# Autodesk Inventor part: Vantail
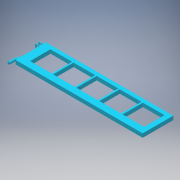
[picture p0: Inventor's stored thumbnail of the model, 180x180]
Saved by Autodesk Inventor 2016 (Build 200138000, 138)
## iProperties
Shininess: 20.0
Length Units: 11269
Angle Units: 11279
Time Units: 11290
Mass Units: 11283
Length Display Precision: 3
Angle Display Precision: 2
Part Number: Vantail
Material: Acier
Document SubType Name: Modeling
Created: 2007-01
Designer: plantier
Mass: 24887.6 g
Surface Area: 3922.97 cm^2
Volume: 3170.39 cm^3
Density: 7.85 g/cm^3
Appearance: Bleu (ciel - vif)
Density: 0.0
Volumn: 0.0
Area: 0.0
PropertySet Name: Model Information
Control State: 0
Master: False
Checked Out: False
Author: plantier
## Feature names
1. Extrusion1
2. Extrusion2
3. Réseau rectangulaire1 [Rectangular Pattern]
4. Extrusion3
5. Congé1 [Fillet]
6. Réseau rectangulaire2 [Rectangular Pattern]
7. Balayage1
8. Extrusion5
9. Extrusion7
## Parameters: d7 = 0, d9 = 169.49153 mm, d12 = 64.93506 mm, d14 = 0, d17 = 181.81818 mm, d18 = 6 mm, d19 = 35 mm, d22 = 0, d23 = 8 mm, d26 = 25 mm, d31 = 0, d35 = 3.79508 mm, d36 = 0.69575 mm, d38 = 13.68948 mm, d39 = 12.8366 mm, d40 = 19.72522 mm, d41 = 15.63719 mm, d42 = 57.90489 mm, d43 = 9.72522 mm, d44 = 42.01351 mm, d49 = 15 mm, d52 = 0, d53 = 0, d56 = 5 mm, d57 = 0
